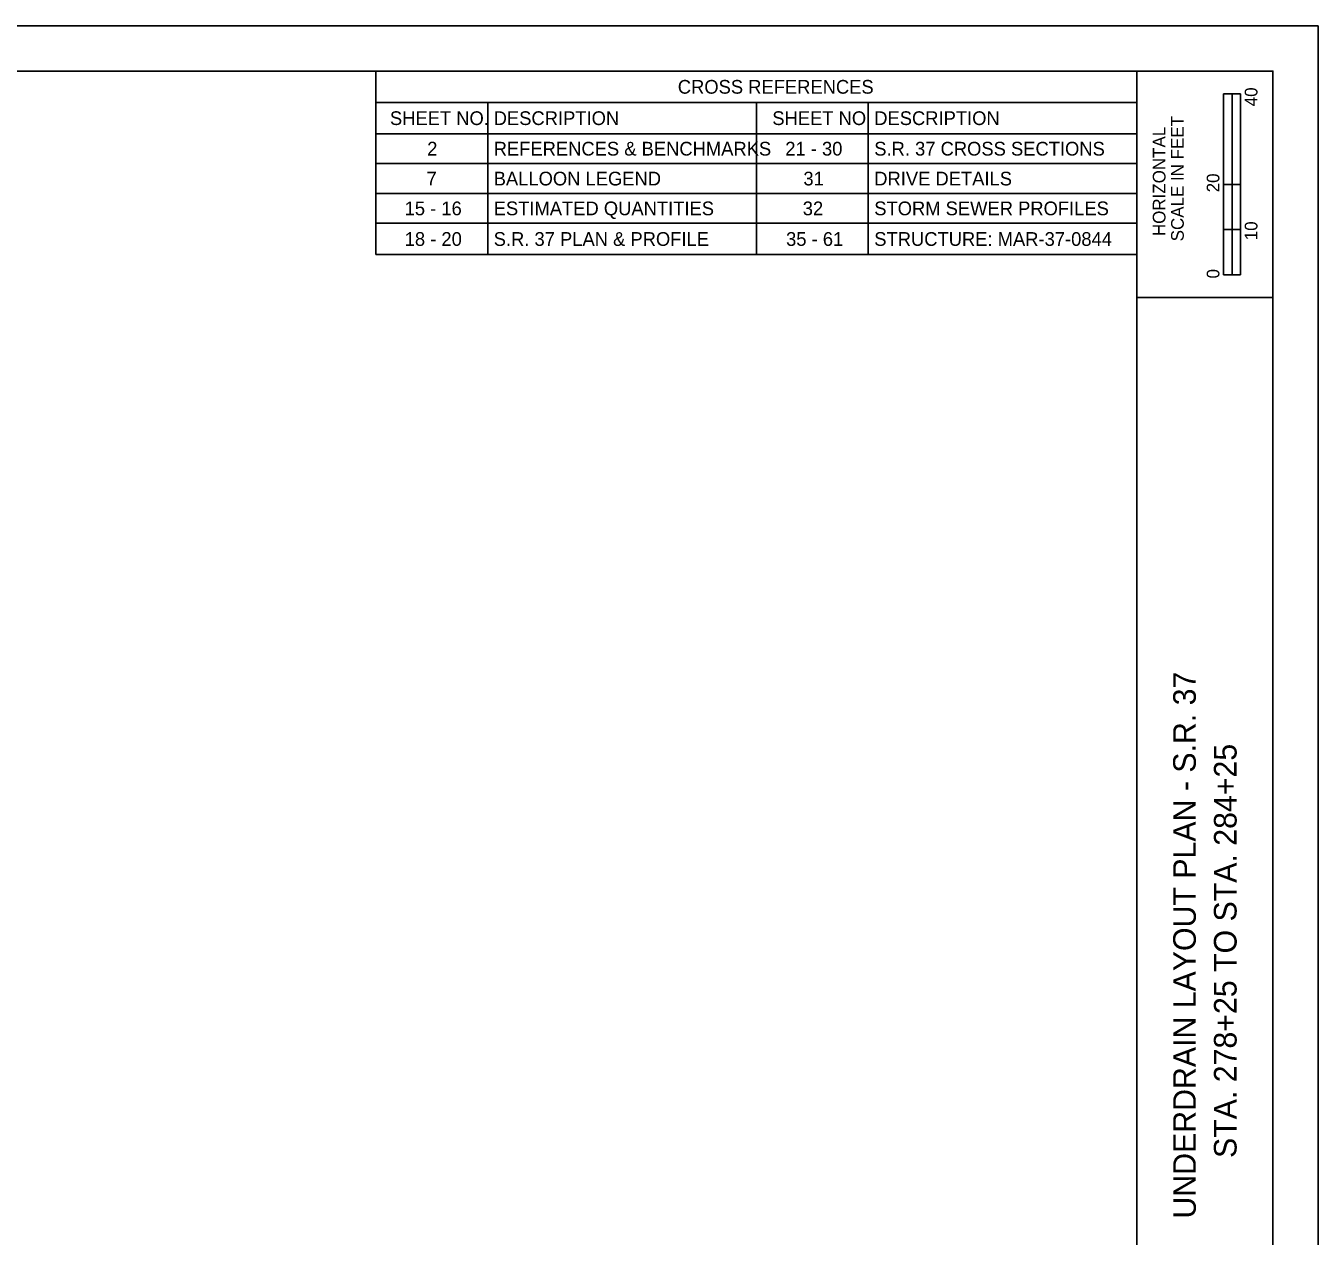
# Model space of a CAD drawing. Extents: x -1.1 to 34, y 0 to 22.
# Drawn here: x 19.74 to 34, y 8.64 to 22 of the extents above; entities that cross this region are included whole.
import ezdxf

# ---------------------------------------------------------------- set-up
doc = ezdxf.new("R2010")
doc.units = 0
for name, color, linetype in [('BR_X_SV_Abut', 7, 'Continuous'), ('CL_X_RW', 7, 'Continuous'), ('RW_X_CL', 7, 'Continuous')]:
    doc.layers.add(name, color=color, linetype=linetype)

msp = doc.modelspace()

# ---------------------------------------------------------------- linework, layer by layer
at = {"layer": 'BR_X_SV_Abut'}
for p, q in [((23.6, 21.5), (32, 21.5)), ((23.6, 21.5), (32, 21.5)), ((23.6, 21.5), (23.6, 19.474)), ((32, 21.5), (32, 19.474)), ((32, 21.5), (32, 19.474)), ((23.6, 21.154), (32, 21.154)), ((24.835, 21.154), (24.835, 19.474)), ((27.8, 21.154), (27.8, 19.474)), ((29.035, 21.154), (29.035, 19.474)), ((32.957, 19.25), (32.957, 21.25)), ((33.144, 21.25), (32.957, 21.25)), ((32.957, 20.25), (32.957, 21.25)), ((32.957, 21.25), (33.05, 21.25)), ((33.05, 21.25), (33.051, 21.25)), ((33.051, 21.25), (33.051, 20.25)), ((33.144, 21.25), (33.144, 19.25)), ((23.6, 20.808), (32, 20.808)), ((23.6, 20.479), (32, 20.479)), ((23.6, 20.149), (32, 20.149)), ((33.051, 20.25), (32.957, 20.25)), ((33.143, 20.25), (33.05, 20.25)), ((33.05, 20.25), (33.05, 19.75)), ((33.143, 19.75), (33.143, 20.25)), ((23.6, 19.82), (32, 19.82)), ((33.05, 19.75), (32.957, 19.75)), ((32.957, 19.75), (32.957, 19.25)), ((33.05, 19.25), (33.05, 19.75)), ((33.05, 19.75), (33.143, 19.75)), ((23.6, 19.474), (32, 19.474)), ((33.144, 19.25), (32.957, 19.25)), ((32.957, 19.25), (33.05, 19.25))]:
    msp.add_line(p, q, dxfattribs=at)
at = {"layer": 'CL_X_RW'}
msp.add_lwpolyline([(0, 0), (34, 0), (34, 22), (0, 22)], close=True, dxfattribs=at)
at = {"layer": 'RW_X_CL'}
for p, q in [((32, 0.5), (32, 21.5)), ((32, 19), (33.5, 19))]:
    msp.add_line(p, q, dxfattribs=at)
msp.add_lwpolyline([(1.5, 21.5), (33.5, 21.5), (33.5, 0.5), (1.5, 0.5)], close=True, dxfattribs=at)

# ---------------------------------------------------------------- texts
at = {"layer": 'BR_X_SV_Abut'}
for s, height, p in [('CROSS REFERENCES', 0.15153, (26.933, 21.251)), ('SHEET NO.', 0.1515, (23.756, 20.905)), ('DESCRIPTION', 0.15153, (24.901, 20.905)), ('SHEET NO', 0.1515, (27.976, 20.905)), ('DESCRIPTION', 0.15153, (29.101, 20.905)), ('2', 0.152, (24.167, 20.568)), ('REFERENCES & BENCHMARKS', 0.15153, (24.901, 20.568)), ('21 - 30', 0.1515, (28.119, 20.568)), ('S.R. 37 CROSS SECTIONS', 0.15153, (29.101, 20.568)), ('7', 0.152, (24.16, 20.238)), ('BALLOON LEGEND', 0.15153, (24.901, 20.238)), ('31', 0.1515, (28.319, 20.238)), ('DRIVE DETAILS', 0.15153, (29.101, 20.238)), ('15 - 16', 0.1515, (23.918, 19.909)), ('ESTIMATED QUANTITIES', 0.15153, (24.901, 19.909)), ('32', 0.1515, (28.312, 19.909)), ('STORM SEWER PROFILES', 0.15153, (29.101, 19.909)), ('18 - 20', 0.1515, (23.919, 19.571)), ('S.R. 37 PLAN & PROFILE', 0.15153, (24.901, 19.571)), ('35 - 61', 0.1515, (28.128, 19.571)), ('STRUCTURE: MAR-37-0844', 0.15153, (29.101, 19.571))]:
    msp.add_text(s, height=height, dxfattribs=at).set_placement(p)
for s, height, p in [('40', 0.14, (33.33, 21.112)), ('SCALE IN FEET', 0.14, (32.517, 19.621)), ('HORIZONTAL', 0.14, (32.315, 19.679)), ('20', 0.14, (32.91, 20.162)), ('10', 0.14, (33.33, 19.633)), ('0', 0.14, (32.91, 19.211)), ('UNDERDRAIN LAYOUT PLAN - S.R. 37', 0.25, (32.65, 8.833)), ('STA. 278+25 TO STA. 284+25', 0.25, (33.1, 9.502))]:
    msp.add_text(s, height=height, rotation=90, dxfattribs=at).set_placement(p)

doc.saveas('drawing.dxf')
